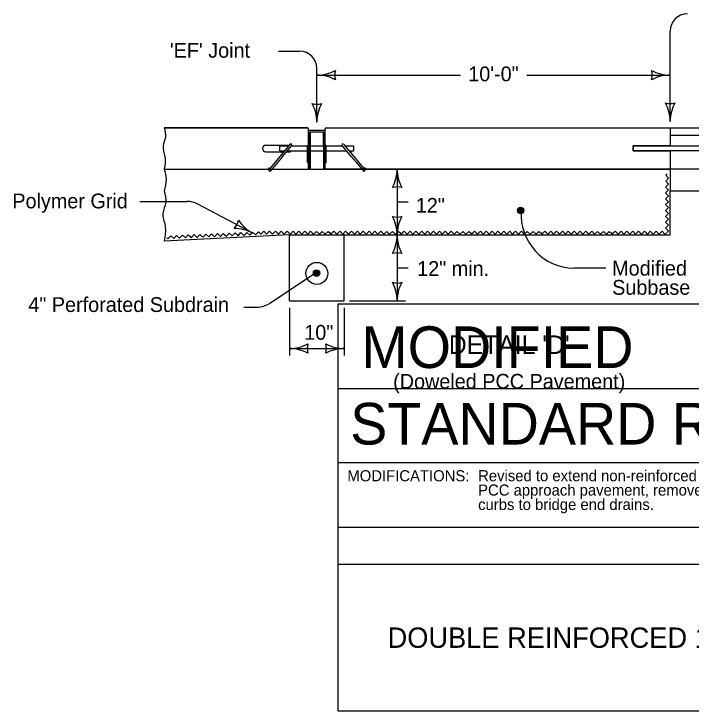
# Model space of a CAD drawing. Extents: x 10130 to 81668, y 5440 to 21644.
# Drawn here: x 15737 to 16469, y 10042 to 10795 of the extents above; entities that cross this region are included whole.
import ezdxf

# ---------------------------------------------------------------- set-up
doc = ezdxf.new("R2010")
doc.units = 0
for name, color, linetype in [('dsnNonPlotable', 7, 'Continuous'), ('dsnStdBlock', 7, 'Continuous'), ('dsnStdBlockModified', 7, 'Continuous'), ('dsnStdBlockNotModified', 7, 'Continuous'), ('dsnStdBorder', 7, 'Continuous'), ('dsnStdLabel', 7, 'Continuous'), ('Level 1', 7, 'Continuous')]:
    doc.layers.add(name, color=color, linetype=linetype)

msp = doc.modelspace()

# ---------------------------------------------------------------- linework, layer by layer
at = {"layer": 'dsnNonPlotable'}
for p, q in [((16064.12, 10729.2), (16219.31, 10729.2)), ((16290.92, 10729.2), (16446, 10729.2))]:
    msp.add_line(p, q, dxfattribs=at)
for centre, radius, start, end in [((16064.12, 10771.95), 42.75, 270, 298.07249), ((16099.96, 10729.2), 16.51, 162.26665, 197.73335), ((16410.15, 10729.2), 16.51, 342.26665, 17.73335), ((16446, 10771.95), 42.75, 241.92751, 270), ((16064.12, 10686.45), 42.75, 61.92751, 90), ((16446, 10686.45), 42.75, 90, 118.07249)]:
    msp.add_arc(centre, radius, start, end, dxfattribs=at)
at = {"layer": 'dsnStdBlock'}
for p, q in [((15899.11, 10672.29), (16053.96, 10672.29)), ((16055.2, 10641.28), (16055.2, 10671.04)), ((16055.2, 10669.88), (16073.02, 10669.88)), ((16073.02, 10641.28), (16073.02, 10671.04)), ((16074.27, 10672.29), (16446, 10672.29)), ((16446, 10672.29), (16617.71, 10672.29)), ((16446, 10672.29), (16446, 10652.8)), ((16055.2, 10667.48), (16056.99, 10667.48)), ((16055.38, 10667.48), (16055.38, 10641.28)), ((16055.56, 10667.48), (16055.56, 10641.28)), ((16055.74, 10667.48), (16055.74, 10641.28)), ((16055.92, 10667.48), (16055.92, 10641.28)), ((16056.1, 10667.48), (16056.1, 10641.28)), ((16056.27, 10667.48), (16056.27, 10641.28)), ((16056.45, 10667.48), (16056.45, 10641.28)), ((16056.63, 10667.48), (16056.63, 10641.28)), ((16056.81, 10667.48), (16056.81, 10641.28)), ((16056.99, 10667.48), (16056.99, 10652.69)), ((16071.24, 10667.48), (16056.99, 10667.48)), ((16056.99, 10667.48), (16056.99, 10652.69)), ((16071.24, 10667.48), (16071.24, 10652.69)), ((16071.24, 10652.69), (16071.24, 10667.48)), ((16071.24, 10667.48), (16073.02, 10667.48)), ((16071.42, 10667.48), (16071.42, 10641.28)), ((16071.6, 10667.48), (16071.6, 10641.28)), ((16071.78, 10667.48), (16071.78, 10641.28)), ((16071.96, 10667.48), (16071.96, 10641.28)), ((16072.13, 10667.48), (16072.13, 10641.28)), ((16072.31, 10667.48), (16072.31, 10641.28)), ((16072.49, 10667.48), (16072.49, 10641.28)), ((16072.67, 10667.48), (16072.67, 10641.28)), ((16072.85, 10667.48), (16072.85, 10641.28)), ((16446, 10664.25), (16621.73, 10664.25)), ((16008.87, 10653.58), (16034.57, 10653.58)), ((16024.02, 10647.34), (16024.02, 10652.69)), ((16024.02, 10652.69), (16033.82, 10652.69)), ((16024.02, 10647.34), (16029.34, 10647.34)), ((16035.29, 10654.44), (16024.25, 10641.28)), ((16027.04, 10641.28), (16036.93, 10653.07)), ((16032.13, 10647.34), (16054.14, 10647.34)), ((16033.82, 10652.69), (16033.82, 10652.69)), ((16035.6, 10647.34), (16035.6, 10646.45)), ((16036.61, 10652.69), (16054.14, 10652.69)), ((16054.14, 10634.87), (16054.14, 10652.69)), ((16054.67, 10653.22), (16054.67, 10653.22)), ((16056.99, 10652.69), (16056.99, 10647.34)), ((16056.99, 10652.69), (16071.24, 10652.69)), ((16056.99, 10647.34), (16071.24, 10647.34)), ((16056.99, 10647.34), (16056.99, 10641.28)), ((16071.24, 10652.69), (16071.24, 10647.34)), ((16071.24, 10647.34), (16071.24, 10641.28)), ((16074.09, 10634.87), (16074.09, 10652.69)), ((16074.09, 10652.69), (16091.62, 10652.69)), ((16074.09, 10651.98), (16074.09, 10651.98)), ((16074.09, 10647.34), (16096.1, 10647.34)), ((16101.18, 10641.28), (16091.3, 10653.07)), ((16092.94, 10654.44), (16103.98, 10641.28)), ((16094.41, 10652.69), (16094.41, 10652.69)), ((16094.41, 10652.69), (16104.21, 10652.69)), ((16098.89, 10647.34), (16104.21, 10647.34)), ((16104.21, 10647.34), (16104.21, 10652.69)), ((16405.9, 10647.23), (16405.9, 10652.8)), ((16405.9, 10652.8), (16486.09, 10652.8)), ((16486.09, 10647.23), (16405.9, 10647.23)), ((16446, 10647.23), (16446, 10627.74)), ((16008.87, 10646.45), (16028.59, 10646.45)), ((16024.25, 10641.28), (16018.99, 10635.01)), ((16027.04, 10641.28), (16021.78, 10635.01)), ((16031.38, 10646.45), (16035.6, 10646.45)), ((16055.2, 10635.01), (16055.2, 10641.28)), ((16055.38, 10641.28), (16055.38, 10635.01)), ((16055.56, 10641.28), (16055.56, 10635.01)), ((16055.74, 10641.28), (16055.74, 10635.01)), ((16055.92, 10641.28), (16055.92, 10635.01)), ((16056.1, 10641.28), (16056.1, 10635.01)), ((16056.27, 10641.28), (16056.27, 10635.01)), ((16056.45, 10641.28), (16056.45, 10635.01)), ((16056.63, 10641.28), (16056.63, 10635.01)), ((16056.81, 10641.28), (16056.81, 10635.01)), ((16056.99, 10641.28), (16056.99, 10635.01)), ((16071.24, 10641.28), (16071.24, 10635.01)), ((16071.42, 10641.28), (16071.42, 10635.01)), ((16071.6, 10641.28), (16071.6, 10635.01)), ((16071.78, 10641.28), (16071.78, 10635.01)), ((16071.96, 10641.28), (16071.96, 10635.01)), ((16072.13, 10641.28), (16072.13, 10635.01)), ((16072.31, 10641.28), (16072.31, 10635.01)), ((16072.49, 10641.28), (16072.49, 10635.01)), ((16072.67, 10641.28), (16072.67, 10635.01)), ((16072.85, 10641.28), (16072.85, 10635.01)), ((16073.02, 10635.01), (16073.02, 10641.28)), ((16101.18, 10641.28), (16106.45, 10635.01)), ((16103.98, 10641.28), (16109.24, 10635.01)), ((16018.99, 10635.01), (16011.75, 10626.38)), ((16021.78, 10635.01), (16013.39, 10625.01)), ((16054.14, 10634.87), (16054.14, 10634.87)), ((16055.2, 10627.74), (16055.2, 10635.01)), ((16055.38, 10635.01), (16055.38, 10627.74)), ((16055.56, 10635.01), (16055.56, 10627.74)), ((16055.74, 10635.01), (16055.74, 10627.74)), ((16055.92, 10635.01), (16055.92, 10627.74)), ((16056.1, 10635.01), (16056.1, 10627.74)), ((16056.27, 10635.01), (16056.27, 10627.74)), ((16056.45, 10635.01), (16056.45, 10627.74)), ((16056.63, 10635.01), (16056.63, 10627.74)), ((16056.81, 10635.01), (16056.81, 10627.74)), ((16056.99, 10635.01), (16056.99, 10627.74)), ((16071.24, 10635.01), (16071.24, 10627.74)), ((16071.42, 10635.01), (16071.42, 10627.74)), ((16071.6, 10635.01), (16071.6, 10627.74)), ((16071.78, 10635.01), (16071.78, 10627.74)), ((16071.96, 10635.01), (16071.96, 10627.74)), ((16072.13, 10635.01), (16072.13, 10627.74)), ((16072.31, 10635.01), (16072.31, 10627.74)), ((16072.49, 10635.01), (16072.49, 10627.74)), ((16072.67, 10635.01), (16072.67, 10627.74)), ((16072.85, 10635.01), (16072.85, 10627.74)), ((16073.02, 10627.74), (16073.02, 10635.01)), ((16106.45, 10635.01), (16114.84, 10625.01)), ((16109.24, 10635.01), (16116.48, 10626.38)), ((15899.11, 10627.74), (16012.89, 10627.74)), ((16013.39, 10625.01), (16011.75, 10626.38)), ((16015.68, 10627.74), (16056.99, 10627.74)), ((16056.99, 10627.74), (16071.24, 10627.74)), ((16071.24, 10627.74), (16112.55, 10627.74)), ((16114.84, 10625.01), (16116.48, 10626.38)), ((16115.34, 10627.74), (16446, 10627.74)), ((16446, 10627.74), (16446, 10603.98)), ((16620.74, 10627.74), (16446, 10627.74)), ((16446, 10591.53), (16446, 10603.98)), ((16446, 10603.98), (16616.75, 10603.98)), ((16446, 10556.46), (16446, 10591.53)), ((16034.41, 10556.46), (15899.11, 10549.9)), ((16033.79, 10556.46), (16093.19, 10556.46)), ((16034.41, 10485.18), (16034.41, 10556.46)), ((16093.81, 10485.18), (16093.81, 10556.46)), ((16093.81, 10556.46), (16446, 10556.46)), ((16034.41, 10485.18), (16093.81, 10485.18))]:
    msp.add_line(p, q, dxfattribs=at)
for points in [[(16056.99, 10667.34), (16057.13, 10667.48)], [(16056.99, 10647.05), (16057.28, 10647.34)], [(16442.58, 10559.12), (16444.17, 10560.7), (16441.01, 10563.88), (16444.18, 10567.04), (16441.02, 10570.22), (16444.21, 10573.38), (16441.04, 10576.55), (16444.22, 10579.71), (16441.06, 10582.89), (16444.24, 10586.05), (16441.07, 10589.23), (16444.25, 10592.39), (16441.09, 10595.56), (16444.27, 10598.72), (16441.11, 10601.9), (16444.29, 10605.06), (16441.13, 10608.23), (16444.31, 10611.39), (16441.14, 10614.56), (16444.32, 10617.73), (16441.16, 10620.91), (16442.8, 10622.54)], [(15902.01, 10553.45), (15903.17, 10552.38), (15906.19, 10555.69), (15909.5, 10552.65), (15912.53, 10555.96), (15915.83, 10552.94), (15918.86, 10556.23), (15922.16, 10553.21), (15925.19, 10556.5), (15926.83, 10555)], [(15926.68, 10555.02), (15928.33, 10553.5), (15931.36, 10556.8), (15934.66, 10553.77), (15937.69, 10557.08), (15940.99, 10554.05), (15944.02, 10557.35), (15947.32, 10554.33), (15950.35, 10557.62), (15953.65, 10554.6), (15956.68, 10557.9), (15959.98, 10554.87), (15963, 10558.18), (15966.31, 10555.14), (15969.34, 10558.45), (15972.63, 10555.42), (15975.67, 10558.72), (15978.97, 10555.69), (15982, 10558.99), (15985.3, 10555.96), (15988.33, 10559.27), (15991.63, 10556.24), (15994.66, 10559.54), (15997.96, 10556.51), (16000.99, 10559.81), (16002.64, 10558.3)], [(16001.93, 10558.95), (16003.5, 10557.35), (16006.69, 10560.51), (16009.84, 10557.34), (16013.02, 10560.5), (16016.18, 10557.31), (16019.35, 10560.48), (16022.51, 10557.3), (16025.69, 10560.46), (16028.85, 10557.28), (16032.03, 10560.45), (16035.19, 10557.27), (16038.37, 10560.43), (16041.52, 10557.25), (16044.7, 10560.41), (16047.86, 10557.24), (16051.03, 10560.4), (16054.19, 10557.22), (16057.37, 10560.38), (16060.53, 10557.2), (16063.71, 10560.36), (16066.86, 10557.19), (16070.04, 10560.35), (16073.2, 10557.16), (16076.37, 10560.33), (16077.8, 10559.2)], [(16077.79, 10558.95), (16079.37, 10557.35), (16082.55, 10560.51), (16085.71, 10557.34), (16088.89, 10560.5), (16092.05, 10557.31), (16095.22, 10560.48), (16098.38, 10557.3), (16101.56, 10560.46), (16104.72, 10557.28), (16107.9, 10560.45), (16111.06, 10557.27), (16114.23, 10560.43), (16117.39, 10557.25), (16120.57, 10560.41), (16123.73, 10557.24), (16126.9, 10560.4), (16130.06, 10557.22), (16133.23, 10560.38), (16136.4, 10557.2), (16139.58, 10560.36), (16142.73, 10557.19), (16145.91, 10560.35), (16149.07, 10557.16), (16152.24, 10560.33), (16153.67, 10559.2)], [(16153.76, 10558.95), (16155.34, 10557.35), (16158.52, 10560.51), (16161.68, 10557.34), (16164.86, 10560.5), (16168.02, 10557.31), (16171.19, 10560.48), (16174.35, 10557.3), (16177.53, 10560.46), (16180.68, 10557.28), (16183.87, 10560.45), (16187.03, 10557.27), (16190.2, 10560.43), (16193.36, 10557.25), (16196.54, 10560.41), (16199.7, 10557.24), (16202.87, 10560.4), (16206.03, 10557.22), (16209.2, 10560.38), (16212.36, 10557.2), (16215.55, 10560.36), (16218.7, 10557.19), (16221.88, 10560.35), (16225.04, 10557.16), (16228.21, 10560.33), (16229.64, 10559.2)], [(16229.77, 10558.95), (16231.35, 10557.35), (16234.53, 10560.51), (16237.68, 10557.34), (16240.87, 10560.5), (16244.03, 10557.31), (16247.19, 10560.48), (16250.36, 10557.3), (16253.54, 10560.46), (16256.69, 10557.28), (16259.87, 10560.45), (16263.03, 10557.27), (16266.21, 10560.43), (16269.36, 10557.25), (16272.55, 10560.41), (16275.71, 10557.24), (16278.87, 10560.4), (16282.04, 10557.22), (16285.21, 10560.38), (16288.37, 10557.2), (16291.55, 10560.36), (16294.71, 10557.19), (16297.88, 10560.35), (16301.04, 10557.16), (16304.22, 10560.33), (16305.64, 10559.2)], [(16305.79, 10558.95), (16307.37, 10557.35), (16310.55, 10560.51), (16313.7, 10557.34), (16316.88, 10560.5), (16320.04, 10557.31), (16323.21, 10560.48), (16326.37, 10557.3), (16329.56, 10560.46), (16332.71, 10557.28), (16335.89, 10560.45), (16339.05, 10557.27), (16342.23, 10560.43), (16345.38, 10557.25), (16348.56, 10560.41), (16351.72, 10557.24), (16354.89, 10560.4), (16358.05, 10557.22), (16361.23, 10560.38), (16364.39, 10557.2), (16367.57, 10560.36), (16370.73, 10557.19), (16373.9, 10560.35), (16377.06, 10557.16), (16380.24, 10560.33), (16381.66, 10559.2)], [(16381.76, 10558.95), (16383.34, 10557.35), (16386.52, 10560.51), (16389.68, 10557.34), (16392.86, 10560.5), (16396.02, 10557.31), (16399.19, 10560.48), (16402.35, 10557.3), (16405.53, 10560.46), (16408.69, 10557.28), (16411.87, 10560.45), (16415.03, 10557.27), (16418.2, 10560.43), (16421.36, 10557.25), (16424.54, 10560.41), (16427.7, 10557.24), (16430.87, 10560.4), (16434.03, 10557.22), (16437.2, 10560.38), (16440.37, 10557.2), (16442.01, 10558.84)]]:
    msp.add_lwpolyline(points, dxfattribs=at)
for centre, radius in [((16100.42, 10646.63), 0.713), ((16027.06, 10645.74), 0.713), ((16012.56, 10628.45), 0.713), ((16115.68, 10628.45), 0.713), ((16064.12, 10514.88), 11.88)]:
    msp.add_circle(centre, radius, dxfattribs=at)
for centre, radius, start, end in [((16053.96, 10671.04), 1.25, 0, 90), ((16074.27, 10671.04), 1.25, 90, 180), ((16036.12, 10653.76), 1.07, 320.00367, 139.99636), ((16092.12, 10653.76), 1.07, 40.00364, 219.99633), ((16008.87, 10650.02), 3.56, 90, 270), ((16054.67, 10652.69), 0.535, 0, 180), ((16073.56, 10652.69), 0.535, 0, 180), ((16054.67, 10634.87), 0.535, 180, 0), ((16073.56, 10634.87), 0.535, 180, 0)]:
    msp.add_arc(centre, radius, start, end, dxfattribs=at)
for points in [[(15899.11, 10672.29), (15900.47, 10661.99), (15897.9, 10652.62), (15899.87, 10641.43), (15899.11, 10627.74)], [(16074.09, 10652.33), (16074.19, 10652.32), (16074.28, 10652.34), (16074.35, 10652.32), (16074.42, 10652.34), (16074.47, 10652.32), (16074.53, 10652.33)], [(16074.09, 10651.98), (16074.19, 10651.97), (16074.28, 10651.98), (16074.35, 10651.97), (16074.42, 10651.98), (16074.47, 10651.96), (16074.53, 10651.97)], [(16074.09, 10651.62), (16074.19, 10651.61), (16074.28, 10651.62), (16074.35, 10651.61), (16074.42, 10651.63), (16074.47, 10651.61), (16074.53, 10651.62)], [(16074.09, 10651.26), (16074.19, 10651.26), (16074.28, 10651.27), (16074.35, 10651.26), (16074.42, 10651.27), (16074.47, 10651.25), (16074.53, 10651.26)], [(16074.09, 10650.91), (16074.19, 10650.9), (16074.28, 10650.91), (16074.35, 10650.9), (16074.42, 10650.91), (16074.47, 10650.89), (16074.53, 10650.9)], [(16074.09, 10650.55), (16074.19, 10650.54), (16074.28, 10650.55), (16074.35, 10650.54), (16074.42, 10650.56), (16074.47, 10650.54), (16074.53, 10650.55)], [(16074.09, 10650.19), (16074.19, 10650.19), (16074.28, 10650.2), (16074.35, 10650.19), (16074.42, 10650.2), (16074.47, 10650.18), (16074.53, 10650.19)], [(16074.09, 10649.84), (16074.19, 10649.83), (16074.28, 10649.84), (16074.35, 10649.83), (16074.42, 10649.85), (16074.47, 10649.83), (16074.53, 10649.83)], [(16074.09, 10649.48), (16074.19, 10649.47), (16074.28, 10649.49), (16074.35, 10649.47), (16074.42, 10649.49), (16074.47, 10649.47), (16074.53, 10649.48)], [(16074.09, 10649.12), (16074.19, 10649.12), (16074.28, 10649.13), (16074.35, 10649.12), (16074.42, 10649.13), (16074.47, 10649.11), (16074.53, 10649.12)], [(16074.09, 10648.77), (16074.19, 10648.76), (16074.28, 10648.77), (16074.35, 10648.76), (16074.42, 10648.78), (16074.47, 10648.76), (16074.53, 10648.76)], [(16074.09, 10648.41), (16074.19, 10648.4), (16074.28, 10648.42), (16074.35, 10648.4), (16074.42, 10648.42), (16074.47, 10648.4), (16074.53, 10648.41)], [(16074.09, 10648.06), (16074.19, 10648.05), (16074.28, 10648.06), (16074.35, 10648.05), (16074.42, 10648.06), (16074.47, 10648.04), (16074.53, 10648.05)], [(16074.09, 10647.7), (16074.19, 10647.69), (16074.28, 10647.7), (16074.35, 10647.69), (16074.42, 10647.71), (16074.47, 10647.69), (16074.53, 10647.7)], [(15899.11, 10627.74), (15901.08, 10616.8), (15899.11, 10603.98)], [(15899.11, 10603.98), (15900.76, 10591.47), (15897.64, 10580.07), (15900.03, 10566.48), (15899.11, 10549.83)]]:
    msp.add_spline(points, degree=3, dxfattribs=at)
at = {"layer": 'dsnStdBlockModified'}
for p, q in [((16073.02, 10627.74), (16073.03, 10671.04)), ((16073.03, 10671.04), (16073.03, 10671.04)), ((16074.27, 10672.29), (16446, 10672.29)), ((16446, 10672.29), (16445.99, 10652.86)), ((16445.99, 10652.86), (16405.9, 10652.8)), ((16405.9, 10652.8), (16405.9, 10647.23)), ((16405.9, 10647.23), (16445.99, 10647.28)), ((16445.99, 10647.28), (16446, 10627.74)), ((16186.17, 10627.74), (16073.02, 10627.74)), ((16446, 10627.74), (16186.17, 10627.74))]:
    msp.add_line(p, q, dxfattribs=at)
msp.add_lwpolyline([(16073.03, 10671.04), (16073.36, 10672.04), (16074.27, 10672.29)], dxfattribs=at)
at = {"layer": 'dsnStdBlockNotModified'}
for p, q in [((16446, 10679.09), (16446, 10776.79)), ((16022.76, 10755.19), (16045.55, 10755.19)), ((16064.11, 10721.7), (16064.11, 10736.63)), ((16064.11, 10678.43), (16064.11, 10721.7)), ((16150.86, 10627.74), (16150.86, 10556.46)), ((15872.68, 10592.75), (15923.68, 10592.75)), ((15994.79, 10558.46), (15935.36, 10589.85)), ((16150.86, 10592.1), (16162.97, 10592.1)), ((16150.86, 10556.46), (16150.86, 10485.18)), ((16150.86, 10520.82), (16162.97, 10520.82)), ((16376.31, 10520.48), (16341.75, 10520.48)), ((16063.9, 10515.76), (16013.12, 10482.54)), ((16099.39, 10485.18), (16160.01, 10485.18)), ((15985.15, 10478.46), (15999.44, 10478.46)), ((16034.41, 10477.75), (16034.41, 10426.24)), ((16093.81, 10477.75), (16093.81, 10426.24)), ((16034.41, 10433.66), (16093.81, 10433.66))]:
    msp.add_line(p, q, dxfattribs=at)
for points in [[(16284.71, 10579.69), (16283.55, 10580.22), (16281.73, 10580.78), (16281.37, 10582.63), (16281.62, 10584.25), (16282.79, 10585.74), (16284.52, 10585.59), (16286.34, 10585.33), (16287.22, 10583.88), (16287.38, 10582.35), (16286.31, 10580.34), (16284.97, 10580.17), (16283.15, 10580.64), (16281.66, 10581.8), (16281.71, 10583.53), (16282.87, 10584.93), (16284.5, 10585.08), (16286.33, 10584.73), (16286.61, 10583.7), (16286.97, 10582.46), (16286.11, 10580.96), (16284.79, 10581), (16283.27, 10581.24), (16282.17, 10582.09), (16282.73, 10583.6), (16283.87, 10584.49), (16285.41, 10584.55), (16285.79, 10583.72), (16286.27, 10582.79), (16285.52, 10581.59), (16284.4, 10581.32), (16283.39, 10581.85), (16283.32, 10582.98), (16283.85, 10583.78), (16284.88, 10584.06), (16285.38, 10583.63), (16285.67, 10583.01), (16285.13, 10582.11), (16284.41, 10581.93), (16283.71, 10582.35), (16283.83, 10582.96), (16284.35, 10583.35), (16285.06, 10583.33), (16285.05, 10582.82), (16284.43, 10582.54)], [(16063.53, 10512.1), (16064.71, 10512.63), (16066.52, 10513.19), (16066.88, 10515.03), (16066.62, 10516.65), (16065.46, 10518.15), (16063.73, 10518), (16061.91, 10517.74), (16061.03, 10516.29), (16060.87, 10514.76), (16061.95, 10512.75), (16063.28, 10512.58), (16065.1, 10513.05), (16066.6, 10514.21), (16066.54, 10515.94), (16065.38, 10517.33), (16063.75, 10517.49), (16061.93, 10517.13), (16061.65, 10516.1), (16061.28, 10514.87), (16062.13, 10513.36), (16063.46, 10513.4), (16064.98, 10513.65), (16066.08, 10514.5), (16065.52, 10516.01), (16064.37, 10516.9), (16062.85, 10516.95), (16062.47, 10516.13), (16061.98, 10515.2), (16062.73, 10514), (16063.86, 10513.72), (16064.86, 10514.26), (16064.93, 10515.38), (16064.4, 10516.18), (16063.37, 10516.46), (16062.87, 10516.04), (16062.58, 10515.41), (16063.12, 10514.52), (16063.84, 10514.33), (16064.54, 10514.76), (16064.42, 10515.37), (16063.9, 10515.76), (16063.19, 10515.74), (16063.2, 10515.23), (16063.82, 10514.94)]]:
    msp.add_lwpolyline(points, dxfattribs=at)
for centre in [(16284.44, 10582.87), (16063.81, 10515.28)]:
    msp.add_circle(centre, 3.47, dxfattribs=at)
for centre, radius, start, end in [((16464.56, 10776.79), 18.56, 90, 180), ((16045.55, 10736.63), 18.56, 0, 90), ((16064.12, 10714.28), 16.51, 252.26665, 287.73335), ((16021.37, 10678.43), 42.75, 360, 28.07249), ((16106.86, 10678.43), 42.75, 151.92751, 180), ((16446, 10714.94), 16.51, 252.26665, 287.73335), ((16403.25, 10679.09), 42.75, 360, 28.07249), ((16488.75, 10679.09), 42.75, 151.92751, 180), ((16108.11, 10627.74), 42.75, 331.92751, 360), ((16193.6, 10627.74), 42.75, 180, 208.07249), ((16150.86, 10591.9), 16.51, 72.26665, 107.73335), ((15923.68, 10567.75), 25, 62.15482, 90), ((16342.8, 10578.31), 57.84, 175.82568, 268.95811), ((15963.1, 10575.2), 16.51, 314.41301, 349.87971), ((16014.76, 10596.25), 42.75, 214.07387, 242.14636), ((16150.86, 10592.3), 16.51, 252.26665, 287.73335), ((16108.11, 10556.46), 42.75, 360, 28.07249), ((16193.6, 10556.46), 42.75, 151.92751, 180), ((15974.81, 10520.66), 42.75, 62.14636, 90.21885), ((16108.11, 10556.46), 42.75, 331.92751, 360), ((16193.6, 10556.46), 42.75, 180, 208.07249), ((16150.86, 10520.62), 16.51, 72.26665, 107.73335), ((16150.86, 10521.02), 16.51, 252.26665, 287.73335), ((16108.11, 10485.18), 42.75, 360, 28.07249), ((16193.6, 10485.18), 42.75, 151.92751, 180), ((15999.44, 10503.46), 25, 270, 303.19674), ((16034.42, 10476.41), 42.75, 270, 298.07249), ((16070.26, 10433.67), 16.51, 162.26665, 197.73335), ((16057.97, 10433.67), 16.51, 342.26665, 17.73335), ((16093.82, 10476.41), 42.75, 241.92751, 270), ((16034.42, 10390.92), 42.75, 61.92751, 90), ((16093.82, 10390.92), 42.75, 90, 118.07249)]:
    msp.add_arc(centre, radius, start, end, dxfattribs=at)
at = {"layer": 'dsnStdBorder'}
for p, q in [((16053.96, 10672.29), (15899.11, 10672.29)), ((16055.21, 10652.73), (16055.21, 10671.05)), ((16054.14, 10634.87), (16054.14, 10652.69)), ((16055.21, 10627.74), (16055.21, 10634.83)), ((15899.11, 10627.74), (16015.68, 10627.74)), ((16015.68, 10627.74), (16055.21, 10627.74))]:
    msp.add_line(p, q, dxfattribs=at)
for centre, radius, start, end in [((16053.96, 10671.05), 1.25, 360, 90), ((16054.67, 10652.69), 0.535, 3.72515, 180), ((16054.67, 10634.87), 0.535, 180, 355.2519)]:
    msp.add_arc(centre, radius, start, end, dxfattribs=at)
msp.add_spline([(15899.11, 10672.29), (15900.47, 10662), (15897.9, 10652.63), (15899.87, 10641.44), (15899.11, 10627.74)], degree=3, dxfattribs=at)
at = {"layer": 'dsnStdLabel'}
for p, q in [((16087.1, 10390.52), (16564.2, 10390.52)), ((16087.1, 10310.52), (16775.12, 10310.52)), ((16087.1, 10240.52), (16775.12, 10240.52)), ((16087.1, 10200.52), (16775.12, 10200.52)), ((16087.1, 10200.52), (16775.12, 10200.52))]:
    msp.add_line(p, q, dxfattribs=at)
msp.add_lwpolyline([(16087.1, 10481.87), (16775.12, 10481.87), (16775.12, 10041.86), (16087.1, 10041.86)], close=True, dxfattribs=at)

# ---------------------------------------------------------------- texts
at = {"layer": 'dsnNonPlotable'}
msp.add_text('10\'-0"', height=16, dxfattribs=at).set_placement((16227.75, 10722.56))
at = {"layer": 'dsnStdBlock'}
msp.add_text('(Doweled PCC Pavement)', height=16, dxfattribs=at).set_placement((16146.58, 10390.27))
at = {"layer": 'dsnStdBlockModified'}
msp.add_text("DETAIL 'D'", height=20, dxfattribs=at).set_placement((16206.76, 10427.87))
at = {"layer": 'dsnStdBlockNotModified'}
for s, p in [("'EF' Joint", (15905.27, 10748.06)), ('Polymer Grid', (15734.96, 10585.21)), ('12"', (16171.06, 10580.44)), ('12" min.', (16172.55, 10512.19)), ('Modified', (16383.29, 10512.51)), ('Subbase', (16383.29, 10491.8)), ('4" Perforated Subdrain', (15752.26, 10473.21)), ('10"', (16050.53, 10443.16))]:
    msp.add_text(s, height=16, dxfattribs=at).set_placement(p)
at = {"layer": 'dsnStdLabel'}
for s, height, p in [('STANDARD ROAD PLAN', 45.0011, (16100.14, 10329.94)), ('Revised to extend non-reinforced section to match length of existing ', 12, (16238.42, 10290.26)), ('PCC approach pavement, remove fixed abutment detail, and extend ', 12, (16238.42, 10274.73)), ('curbs to bridge end drains.', 12, (16238.42, 10259.2)), ("DOUBLE REINFORCED 12'' APPROACH", 22, (16140.6, 10110.19))]:
    msp.add_text(s, height=height, dxfattribs=at).set_placement(p)
at = {"layer": 'Level 1'}
for s, height, p in [('MODIFIED', 45.001, (16112.19, 10412.65)), ('MODIFICATIONS:', 12, (16097.1, 10290.19))]:
    msp.add_text(s, height=height, dxfattribs=at).set_placement(p)

doc.saveas('drawing.dxf')
